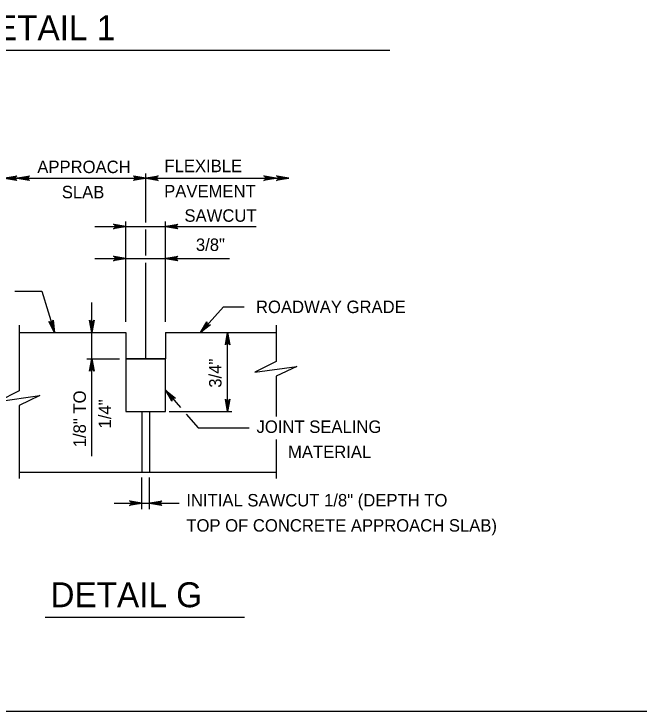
# Model space of a CAD drawing. Extents: x 636530 to 644067, y 294168 to 299122.
# Drawn here: x 639284.8 to 639435.5, y 297153.5 to 297321.5 of the extents above; entities that cross this region are included whole.
import ezdxf

# ---------------------------------------------------------------- set-up
doc = ezdxf.new("R2010")
doc.units = 0
doc.layers.add('1', color=7, linetype='Continuous')

msp = doc.modelspace()

# ---------------------------------------------------------------- linework, layer by layer
at = {"layer": '1'}
for p, q in [((639100.16, 297312.73), (639375.43, 297312.73)), ((639316.59, 297271.23), (639316.59, 297282.99)), ((639282.55, 297281.87), (639316.59, 297281.87)), ((639316.59, 297281.87), (639351.12, 297281.87)), ((639311.82, 297247.23), (639311.82, 297271.48)), ((639321.36, 297247.23), (639321.36, 297271.48)), ((639304.28, 297270.24), (639343.24, 297270.24)), ((639316.59, 297263.22), (639316.59, 297269.53)), ((639304.28, 297262.54), (639336.81, 297262.54)), ((639316.59, 297238.35), (639316.59, 297261.52)), ((639285.04, 297254.69), (639291.5, 297254.69)), ((639291.5, 297254.69), (639294.62, 297244.69)), ((639303.6, 297214.88), (639303.6, 297251.9)), ((639329.77, 297244.69), (639335.32, 297250.88)), ((639335.32, 297250.88), (639340.33, 297250.88)), ((639286.11, 297246.5), (639286.11, 297230.64)), ((639348.07, 297246.5), (639348.07, 297237.67)), ((639286.11, 297244.69), (639311.82, 297244.69)), ((639311.82, 297244.69), (639311.82, 297238.35)), ((639311.82, 297244.69), (639311.82, 297238.35)), ((639321.36, 297244.69), (639348.07, 297244.69)), ((639321.36, 297244.69), (639321.36, 297238.35)), ((639336.33, 297225.64), (639336.33, 297244.69)), ((639302.42, 297238.35), (639310.23, 297238.35)), ((639311.82, 297238.35), (639321.36, 297238.35)), ((639348.07, 297234.15), (639348.07, 297224.44)), ((639321.36, 297230.79), (639324.99, 297226.61)), ((639286.11, 297227.12), (639286.11, 297209.55)), ((639315.68, 297225.64), (639315.68, 297211.02)), ((639317.51, 297225.64), (639317.51, 297211.02)), ((639322.2, 297225.64), (639337.33, 297225.64)), ((639326.35, 297225.05), (639329.23, 297221.74)), ((639329.23, 297221.74), (639341.54, 297221.74)), ((639348.07, 297218.88), (639348.07, 297209.55)), ((639286.11, 297211.02), (639348.07, 297211.02)), ((639315.68, 297202.09), (639315.68, 297209.76)), ((639317.51, 297202.09), (639317.51, 297209.76)), ((639308.94, 297203.57), (639324.67, 297203.57)), ((639292.33, 297176.08), (639340.38, 297176.08)), ((639046.78, 297153.48), (639832.78, 297153.48))]:
    msp.add_line(p, q, dxfattribs=at)
for points in [[(639282.55, 297281.87), (639285.53, 297282.43), (639285.42, 297282.35), (639285.3, 297282.27), (639285.24, 297282.17), (639285.18, 297282.07), (639285.16, 297281.97), (639285.15, 297281.87), (639285.16, 297281.77), (639285.18, 297281.67), (639285.24, 297281.57), (639285.3, 297281.47), (639285.42, 297281.39), (639285.53, 297281.31), (639282.55, 297281.87), (639285.42, 297281.39), (639285.3, 297281.47), (639282.55, 297281.87), (639285.24, 297281.57), (639285.18, 297281.67), (639282.55, 297281.87), (639285.16, 297281.77), (639285.15, 297281.87), (639282.55, 297281.87), (639285.16, 297281.97), (639285.18, 297282.07), (639282.55, 297281.87), (639285.24, 297282.17), (639285.3, 297282.27), (639282.55, 297281.87), (639285.42, 297282.35)], [(639285.6, 297281.87), (639288.58, 297282.43), (639288.46, 297282.35), (639288.35, 297282.27), (639288.29, 297282.17), (639288.23, 297282.07), (639288.21, 297281.97), (639288.2, 297281.87), (639288.21, 297281.77), (639288.23, 297281.67), (639288.29, 297281.57), (639288.35, 297281.47), (639288.46, 297281.39), (639288.58, 297281.31), (639285.6, 297281.87), (639288.46, 297281.39), (639288.35, 297281.47), (639285.6, 297281.87), (639288.29, 297281.57), (639288.23, 297281.67), (639285.6, 297281.87), (639288.21, 297281.77), (639288.2, 297281.87), (639285.6, 297281.87), (639288.21, 297281.97), (639288.23, 297282.07), (639285.6, 297281.87), (639288.29, 297282.17), (639288.35, 297282.27), (639285.6, 297281.87), (639288.46, 297282.35)], [(639316.59, 297281.87), (639313.61, 297281.31), (639313.72, 297281.39), (639313.84, 297281.47), (639313.9, 297281.57), (639313.96, 297281.67), (639313.97, 297281.77), (639313.99, 297281.87), (639313.97, 297281.97), (639313.96, 297282.07), (639313.9, 297282.17), (639313.84, 297282.27), (639313.72, 297282.35), (639313.61, 297282.43), (639316.59, 297281.87), (639313.72, 297282.35), (639313.84, 297282.27), (639316.59, 297281.87), (639313.9, 297282.17), (639313.96, 297282.07), (639316.59, 297281.87), (639313.97, 297281.97), (639313.99, 297281.87), (639316.59, 297281.87), (639313.97, 297281.77), (639313.96, 297281.67), (639316.59, 297281.87), (639313.9, 297281.57), (639313.84, 297281.47), (639316.59, 297281.87), (639313.72, 297281.39)], [(639316.59, 297281.87), (639319.57, 297282.43), (639319.46, 297282.35), (639319.34, 297282.27), (639319.29, 297282.17), (639319.23, 297282.07), (639319.21, 297281.97), (639319.19, 297281.87), (639319.21, 297281.77), (639319.23, 297281.67), (639319.29, 297281.57), (639319.34, 297281.47), (639319.46, 297281.39), (639319.57, 297281.31), (639316.59, 297281.87), (639319.46, 297281.39), (639319.34, 297281.47), (639316.59, 297281.87), (639319.29, 297281.57), (639319.23, 297281.67), (639316.59, 297281.87), (639319.21, 297281.77), (639319.19, 297281.87), (639316.59, 297281.87), (639319.21, 297281.97), (639319.23, 297282.07), (639316.59, 297281.87), (639319.29, 297282.17), (639319.34, 297282.27), (639316.59, 297281.87), (639319.46, 297282.35)], [(639348.07, 297281.87), (639345.09, 297281.31), (639345.2, 297281.39), (639345.32, 297281.47), (639345.38, 297281.57), (639345.44, 297281.67), (639345.45, 297281.77), (639345.47, 297281.87), (639345.45, 297281.97), (639345.44, 297282.07), (639345.38, 297282.17), (639345.32, 297282.27), (639345.2, 297282.35), (639345.09, 297282.43), (639348.07, 297281.87), (639345.2, 297282.35), (639345.32, 297282.27), (639348.07, 297281.87), (639345.38, 297282.17), (639345.44, 297282.07), (639348.07, 297281.87), (639345.45, 297281.97), (639345.47, 297281.87), (639348.07, 297281.87), (639345.45, 297281.77), (639345.44, 297281.67), (639348.07, 297281.87), (639345.38, 297281.57), (639345.32, 297281.47), (639348.07, 297281.87), (639345.2, 297281.39)], [(639351.12, 297281.87), (639348.14, 297281.31), (639348.25, 297281.39), (639348.37, 297281.47), (639348.42, 297281.57), (639348.48, 297281.67), (639348.5, 297281.77), (639348.52, 297281.87), (639348.5, 297281.97), (639348.48, 297282.07), (639348.42, 297282.17), (639348.37, 297282.27), (639348.25, 297282.35), (639348.14, 297282.43), (639351.12, 297281.87), (639348.25, 297282.35), (639348.37, 297282.27), (639351.12, 297281.87), (639348.42, 297282.17), (639348.48, 297282.07), (639351.12, 297281.87), (639348.5, 297281.97), (639348.52, 297281.87), (639351.12, 297281.87), (639348.5, 297281.77), (639348.48, 297281.67), (639351.12, 297281.87), (639348.42, 297281.57), (639348.37, 297281.47), (639351.12, 297281.87), (639348.25, 297281.39)], [(639311.82, 297270.24), (639308.84, 297269.68), (639308.95, 297269.76), (639309.07, 297269.84), (639309.13, 297269.94), (639309.19, 297270.04), (639309.2, 297270.14), (639309.22, 297270.24), (639309.2, 297270.34), (639309.19, 297270.44), (639309.13, 297270.54), (639309.07, 297270.64), (639308.95, 297270.72), (639308.84, 297270.8), (639311.82, 297270.24), (639308.95, 297270.72), (639309.07, 297270.64), (639311.82, 297270.24), (639309.13, 297270.54), (639309.19, 297270.44), (639311.82, 297270.24), (639309.2, 297270.34), (639309.22, 297270.24), (639311.82, 297270.24), (639309.2, 297270.14), (639309.19, 297270.04), (639311.82, 297270.24), (639309.13, 297269.94), (639309.07, 297269.84), (639311.82, 297270.24), (639308.95, 297269.76)], [(639321.36, 297270.24), (639324.34, 297270.8), (639324.23, 297270.72), (639324.11, 297270.64), (639324.06, 297270.54), (639324, 297270.44), (639323.98, 297270.34), (639323.96, 297270.24), (639323.98, 297270.14), (639324, 297270.04), (639324.06, 297269.94), (639324.11, 297269.84), (639324.23, 297269.76), (639324.34, 297269.68), (639321.36, 297270.24), (639324.23, 297269.76), (639324.11, 297269.84), (639321.36, 297270.24), (639324.06, 297269.94), (639324, 297270.04), (639321.36, 297270.24), (639323.98, 297270.14), (639323.96, 297270.24), (639321.36, 297270.24), (639323.98, 297270.34), (639324, 297270.44), (639321.36, 297270.24), (639324.06, 297270.54), (639324.11, 297270.64), (639321.36, 297270.24), (639324.23, 297270.72)], [(639311.82, 297262.54), (639308.84, 297261.98), (639308.95, 297262.06), (639309.07, 297262.14), (639309.13, 297262.24), (639309.19, 297262.34), (639309.2, 297262.44), (639309.22, 297262.54), (639309.2, 297262.64), (639309.19, 297262.74), (639309.13, 297262.84), (639309.07, 297262.94), (639308.95, 297263.02), (639308.84, 297263.1), (639311.82, 297262.54), (639308.95, 297263.02), (639309.07, 297262.94), (639311.82, 297262.54), (639309.13, 297262.84), (639309.19, 297262.74), (639311.82, 297262.54), (639309.2, 297262.64), (639309.22, 297262.54), (639311.82, 297262.54), (639309.2, 297262.44), (639309.19, 297262.34), (639311.82, 297262.54), (639309.13, 297262.24), (639309.07, 297262.14), (639311.82, 297262.54), (639308.95, 297262.06)], [(639321.36, 297262.54), (639324.34, 297263.1), (639324.23, 297263.02), (639324.11, 297262.94), (639324.06, 297262.84), (639324, 297262.74), (639323.98, 297262.64), (639323.96, 297262.54), (639323.98, 297262.44), (639324, 297262.34), (639324.06, 297262.24), (639324.11, 297262.14), (639324.23, 297262.06), (639324.34, 297261.98), (639321.36, 297262.54), (639324.23, 297262.06), (639324.11, 297262.14), (639321.36, 297262.54), (639324.06, 297262.24), (639324, 297262.34), (639321.36, 297262.54), (639323.98, 297262.44), (639323.96, 297262.54), (639321.36, 297262.54), (639323.98, 297262.64), (639324, 297262.74), (639321.36, 297262.54), (639324.06, 297262.84), (639324.11, 297262.94), (639321.36, 297262.54), (639324.23, 297263.02)], [(639294.62, 297244.69), (639293.2, 297247.37), (639293.31, 297247.28), (639293.42, 297247.19), (639293.53, 297247.17), (639293.65, 297247.14), (639293.75, 297247.15), (639293.85, 297247.17), (639293.94, 297247.21), (639294.03, 297247.26), (639294.11, 297247.35), (639294.18, 297247.43), (639294.22, 297247.57), (639294.27, 297247.7), (639294.62, 297244.69), (639294.22, 297247.57), (639294.18, 297247.43), (639294.62, 297244.69), (639294.11, 297247.35), (639294.03, 297247.26), (639294.62, 297244.69), (639293.94, 297247.21), (639293.85, 297247.17), (639294.62, 297244.69), (639293.75, 297247.15), (639293.65, 297247.14), (639294.62, 297244.69), (639293.53, 297247.17), (639293.42, 297247.19), (639294.62, 297244.69), (639293.31, 297247.28)], [(639303.6, 297244.69), (639303.04, 297247.67), (639303.2, 297247.44), (639303.4, 297247.32), (639303.6, 297247.29), (639303.8, 297247.32), (639304, 297247.44), (639304.16, 297247.67), (639303.6, 297244.69), (639304, 297247.44), (639303.8, 297247.32), (639303.6, 297244.69), (639303.6, 297247.29), (639303.4, 297247.32), (639303.6, 297244.69), (639303.2, 297247.44)], [(639329.77, 297244.69), (639331.35, 297247.28), (639331.31, 297247), (639331.38, 297246.78), (639331.51, 297246.62), (639331.68, 297246.51), (639331.91, 297246.47), (639332.18, 297246.53), (639329.77, 297244.69), (639331.91, 297246.47), (639331.68, 297246.51), (639329.77, 297244.69), (639331.51, 297246.62), (639331.38, 297246.78), (639329.77, 297244.69), (639331.31, 297247)], [(639336.33, 297244.69), (639336.89, 297241.7), (639336.73, 297241.93), (639336.53, 297242.05), (639336.33, 297242.09), (639336.13, 297242.05), (639335.93, 297241.93), (639335.78, 297241.7), (639336.33, 297244.69), (639335.93, 297241.93), (639336.13, 297242.05), (639336.33, 297244.69), (639336.33, 297242.09), (639336.53, 297242.05), (639336.33, 297244.69), (639336.73, 297241.93)], [(639303.6, 297238.35), (639304.16, 297235.36), (639304, 297235.59), (639303.8, 297235.71), (639303.6, 297235.75), (639303.4, 297235.71), (639303.2, 297235.59), (639303.04, 297235.36), (639303.6, 297238.35), (639303.2, 297235.59), (639303.4, 297235.71), (639303.6, 297238.35), (639303.6, 297235.75), (639303.8, 297235.71), (639303.6, 297238.35), (639304, 297235.59)], [(639348.07, 297237.67), (639342.88, 297235.13), (639353.03, 297236.51), (639348.07, 297234.15)], [(639286.11, 297230.64), (639280.92, 297228.1), (639291.07, 297229.48), (639286.11, 297227.12)], [(639321.36, 297230.79), (639323.74, 297228.91), (639323.6, 297228.94), (639323.47, 297228.98), (639323.36, 297228.96), (639323.24, 297228.94), (639323.15, 297228.88), (639323.07, 297228.83), (639323, 297228.75), (639322.94, 297228.67), (639322.9, 297228.56), (639322.87, 297228.45), (639322.88, 297228.32), (639322.9, 297228.18), (639321.36, 297230.79), (639322.88, 297228.32), (639322.87, 297228.45), (639321.36, 297230.79), (639322.9, 297228.56), (639322.94, 297228.67), (639321.36, 297230.79), (639323, 297228.75), (639323.07, 297228.83), (639321.36, 297230.79), (639323.15, 297228.88), (639323.24, 297228.94), (639321.36, 297230.79), (639323.36, 297228.96), (639323.47, 297228.98), (639321.36, 297230.79), (639323.6, 297228.94)], [(639336.33, 297225.64), (639335.78, 297228.62), (639335.93, 297228.39), (639336.13, 297228.27), (639336.33, 297228.24), (639336.53, 297228.27), (639336.73, 297228.39), (639336.89, 297228.62), (639336.33, 297225.64), (639336.73, 297228.39), (639336.53, 297228.27), (639336.33, 297225.64), (639336.33, 297228.24), (639336.13, 297228.27), (639336.33, 297225.64), (639335.93, 297228.39)], [(639315.68, 297203.57), (639312.69, 297203.01), (639312.81, 297203.09), (639312.92, 297203.17), (639312.98, 297203.27), (639313.04, 297203.37), (639313.06, 297203.47), (639313.08, 297203.57), (639313.06, 297203.67), (639313.04, 297203.77), (639312.98, 297203.87), (639312.92, 297203.97), (639312.81, 297204.05), (639312.69, 297204.13), (639315.68, 297203.57), (639312.81, 297204.05), (639312.92, 297203.97), (639315.68, 297203.57), (639312.98, 297203.87), (639313.04, 297203.77), (639315.68, 297203.57), (639313.06, 297203.67), (639313.08, 297203.57), (639315.68, 297203.57), (639313.06, 297203.47), (639313.04, 297203.37), (639315.68, 297203.57), (639312.98, 297203.27), (639312.92, 297203.17), (639315.68, 297203.57), (639312.81, 297203.09)], [(639317.51, 297203.57), (639320.49, 297204.13), (639320.37, 297204.05), (639320.26, 297203.97), (639320.2, 297203.87), (639320.14, 297203.77), (639320.12, 297203.67), (639320.11, 297203.57), (639320.12, 297203.47), (639320.14, 297203.37), (639320.2, 297203.27), (639320.26, 297203.17), (639320.37, 297203.09), (639320.49, 297203.01), (639317.51, 297203.57), (639320.37, 297203.09), (639320.26, 297203.17), (639317.51, 297203.57), (639320.2, 297203.27), (639320.14, 297203.37), (639317.51, 297203.57), (639320.12, 297203.47), (639320.11, 297203.57), (639317.51, 297203.57), (639320.12, 297203.67), (639320.14, 297203.77), (639317.51, 297203.57), (639320.2, 297203.87), (639320.26, 297203.97), (639317.51, 297203.57), (639320.37, 297204.05)]]:
    msp.add_lwpolyline(points, dxfattribs=at)
msp.add_lwpolyline([(639311.82, 297225.64), (639321.36, 297225.64), (639321.36, 297238.35), (639311.82, 297238.35)], close=True, dxfattribs=at)

# ---------------------------------------------------------------- texts
for s, height, p in [('TYPE 2 APPROACH SLAB (WITH OVERLAY) - DETAIL 1', 6, (639101.46, 297315.14)), ('APPROACH', 3, (639290.44, 297283.11)), ('FLEXIBLE', 3, (639321.1, 297283.33)), ('SLAB', 3, (639296.35, 297277.04)), ('PAVEMENT', 3, (639321.03, 297277.26)), ('SAWCUT', 3, (639325.92, 297271.38)), ('3/8"', 3, (639328.68, 297264.35)), ('ROADWAY GRADE', 3, (639343.16, 297249.38)), ('JOINT SEALING', 3, (639343.3, 297220.5)), ('MATERIAL', 3, (639350.89, 297214.43)), ('INITIAL SAWCUT 1/8" (DEPTH TO', 3, (639326.37, 297202.78)), ('TOP OF CONCRETE APPROACH SLAB)', 3, (639326.37, 297196.71)), ('DETAIL G', 6, (639293.61, 297178.5))]:
    msp.add_text(s, height=height, dxfattribs=at).set_placement(p)
for s, p in [('3/4"', (639334.85, 297231.39)), ('1/8" TO', (639302.15, 297217.04)), ('1/4"', (639308.22, 297221.58))]:
    msp.add_text(s, height=3, rotation=90, dxfattribs=at).set_placement(p)

doc.saveas('drawing.dxf')
